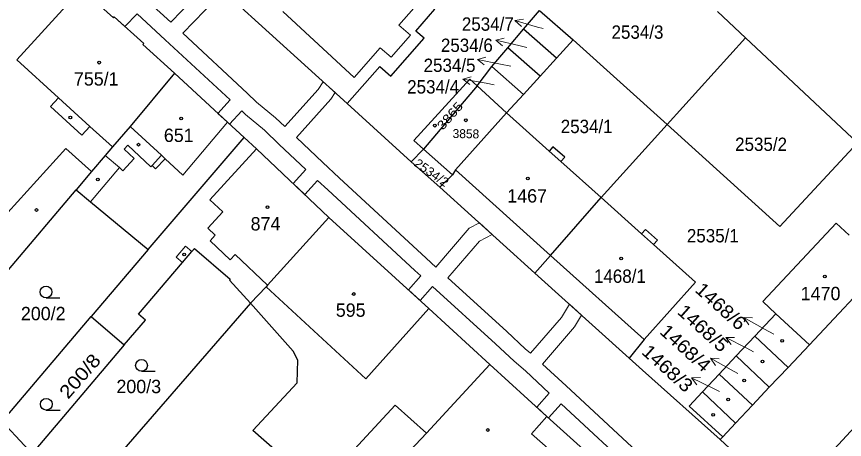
# Model space of a CAD drawing. Extents: x -679733 to -673243, y -1075091 to -1066557.
# Drawn here: x -676350.9 to -676245.5, y -1071162.3 to -1071108.5 of the extents above; entities that cross this region are included whole.
import ezdxf
from ezdxf.enums import TextEntityAlignment as Align

# ---------------------------------------------------------------- set-up
doc = ezdxf.new("R2010")
doc.units = 0
doc.header["$LTSCALE"] = 0.68
for name, color, linetype, lineweight in [('1', 7, 'Continuous', 25), ('13', 7, 'Continuous', 13), ('3', 7, 'Continuous', 25), ('4', 7, 'Continuous', 13), ('5', 7, 'Continuous', 25), ('7', 7, 'Continuous', 13)]:
    doc.layers.add(name, color=color, linetype=linetype, lineweight=lineweight)
doc.layers.add('2', color=7, linetype='Continuous')

msp = doc.modelspace()

# ---------------------------------------------------------------- linework, layer by layer
at = {"layer": '1'}
for p, q in [((-676323.75, -1071105.96), (-676308.77, -1071119.56)), ((-676286.33, -1071110.08), (-676284.31, -1071107.69)), ((-676284.31, -1071107.69), (-676280.02, -1071111.43)), ((-676282.12, -1071113.76), (-676286.33, -1071110.08)), ((-676268.05, -1071122.23), (-676258.07, -1071111.18)), ((-676284.22, -1071116.07), (-676288.34, -1071112.45)), ((-676286.33, -1071118.4), (-676290.36, -1071114.84)), ((-676292.22, -1071117.29), (-676299.05, -1071125.35)), ((-676292.22, -1071117.29), (-676288.48, -1071120.73)), ((-676308.77, -1071119.56), (-676300.62, -1071126.96)), ((-676295.38, -1071128.61), (-676299.05, -1071125.35)), ((-676295.38, -1071128.61), (-676296.99, -1071130.21)), ((-676352.68, -1071160), (-676341.37, -1071146.67)), ((-676249.94, -1071150.27), (-676254.22, -1071146.3)), ((-676252.66, -1071153.13), (-676256.88, -1071149.16)), ((-676337.15, -1071150.27), (-676348.88, -1071164.08)), ((-676255.04, -1071155.66), (-676259.26, -1071151.68)), ((-676257.2, -1071157.96), (-676261.43, -1071153.98)), ((-676260.97, -1071161.98), (-676261.28, -1071162.3))]:
    msp.add_line(p, q, dxfattribs=at)
for points in [[(-676352.93, -1071095.49), (-676342.59, -1071104.93), (-676338.52, -1071108.62), (-676338.42, -1071108.51), (-676334.67, -1071111.91), (-676334.77, -1071112.02), (-676330.76, -1071115.67)], [(-676308.77, -1071119.56), (-676304.62, -1071114.85), (-676303.22, -1071116.08), (-676298.98, -1071111.24), (-676300.04, -1071110.32), (-676297.6, -1071107.53), (-676298.57, -1071106.68), (-676296.84, -1071104.7), (-676301.82, -1071100.3), (-676301.85, -1071099.66), (-676302.05, -1071098.98), (-676302.33, -1071098.37), (-676302.65, -1071097.93), (-676303, -1071097.59), (-676303.32, -1071097.34)], [(-676261.62, -1071107.83), (-676258.07, -1071111.18), (-676243.8, -1071124.53), (-676238.45, -1071129.5), (-676236.29, -1071127.21), (-676234.12, -1071124.91), (-676233.88, -1071124.66), (-676231.56, -1071122.19), (-676229.54, -1071120.04)], [(-676290.36, -1071114.84), (-676288.34, -1071112.45), (-676286.33, -1071110.08)], [(-676268.05, -1071122.23), (-676280.02, -1071111.43), (-676282.12, -1071113.76), (-676284.22, -1071116.07)], [(-676293.17, -1071116.43), (-676292.22, -1071117.29), (-676290.36, -1071114.84)], [(-676330.76, -1071115.67), (-676336.39, -1071122.45), (-676338.67, -1071125.07), (-676339.6, -1071126.16), (-676341.33, -1071128.21), (-676343.28, -1071130.53)], [(-676330.76, -1071115.67), (-676324.03, -1071121.93), (-676321.9, -1071123.86)], [(-676300.62, -1071126.96), (-676299.05, -1071125.35), (-676300.28, -1071124.26), (-676293.17, -1071116.43)], [(-676284.22, -1071116.07), (-676286.33, -1071118.4), (-676288.48, -1071120.73)], [(-676288.48, -1071120.73), (-676294.99, -1071127.98), (-676295.38, -1071128.61)], [(-676276.45, -1071131.52), (-676281.57, -1071126.93), (-676281.09, -1071126.39), (-676282.58, -1071125.06), (-676283.06, -1071125.59), (-676288.48, -1071120.73)], [(-676243.8, -1071124.53), (-676253.69, -1071135.2), (-676268.05, -1071122.23), (-676276.45, -1071131.52)], [(-676343.28, -1071130.53), (-676341.44, -1071132.06), (-676334.13, -1071138.13), (-676321.9, -1071123.86)], [(-676321.9, -1071123.86), (-676320.3, -1071125.31), (-676311.12, -1071134.06)], [(-676296.99, -1071130.21), (-676298.47, -1071128.87), (-676300.62, -1071126.96)], [(-676261.28, -1071162.3), (-676271.19, -1071153.48), (-676272.88, -1071151.94), (-676284.89, -1071141.12), (-676296.99, -1071130.21)], [(-676360.58, -1071151.05), (-676352.91, -1071141.95), (-676351.88, -1071140.73), (-676343.28, -1071130.53)], [(-676284.89, -1071141.12), (-676282.91, -1071138.87), (-676276.45, -1071131.52)], [(-676276.45, -1071131.52), (-676271.31, -1071136.13), (-676270.81, -1071135.57), (-676269.28, -1071136.94), (-676269.78, -1071137.5), (-676264.42, -1071142.3), (-676270.96, -1071149.6), (-676272.88, -1071151.94)], [(-676311.12, -1071134.06), (-676318.9, -1071142.67), (-676319.1, -1071142.89), (-676321.1, -1071144.95)], [(-676311.12, -1071134.06), (-676298.38, -1071145.63), (-676290.61, -1071152.76)], [(-676204.87, -1071134.4), (-676225.85, -1071157.13), (-676233.8, -1071149.8), (-676237.15, -1071146.9), (-676235.55, -1071144.96), (-676240.55, -1071140.25), (-676249.94, -1071150.27), (-676252.66, -1071153.13), (-676255.04, -1071155.66), (-676257.2, -1071157.96)], [(-676254.22, -1071146.3), (-676255.85, -1071144.76), (-676246.53, -1071134.79), (-676244.88, -1071136.32)], [(-676334.13, -1071138.13), (-676341.37, -1071146.67), (-676337.15, -1071150.27)], [(-676337.15, -1071150.27), (-676334.47, -1071147.13), (-676335.36, -1071146.37), (-676329.74, -1071139.77), (-676328.57, -1071138.4), (-676328.23, -1071138.01), (-676323.67, -1071141.9), (-676323.77, -1071142.01), (-676321.1, -1071144.95)], [(-676321.1, -1071144.95), (-676343.05, -1071170.28), (-676338.56, -1071174.86)], [(-676308.33, -1071171.79), (-676309.88, -1071170.43), (-676312.17, -1071168.21), (-676312.43, -1071168.49), (-676320.8, -1071161.16), (-676315.15, -1071155.09), (-676315.05, -1071152.2), (-676315.65, -1071151.06), (-676321.1, -1071144.95)], [(-676261.43, -1071153.98), (-676259.26, -1071151.68), (-676256.88, -1071149.16), (-676254.22, -1071146.3)], [(-676302.23, -1071165.27), (-676298.66, -1071161.49), (-676290.61, -1071152.76)], [(-676290.61, -1071152.76), (-676283.35, -1071159.37), (-676279.12, -1071163.2), (-676277.21, -1071164.93), (-676274.24, -1071167.63)], [(-676260.97, -1071161.98), (-676265.26, -1071158.08), (-676263.54, -1071156.24), (-676261.43, -1071153.98)], [(-676257.2, -1071157.96), (-676259.34, -1071160.23), (-676260.97, -1071161.98)], [(-676348.88, -1071164.08), (-676349.85, -1071163.07), (-676352.68, -1071160)], [(-676261.28, -1071162.3), (-676252.88, -1071170.12), (-676253.02, -1071170.27), (-676249.35, -1071173.7), (-676249.45, -1071173.81), (-676249.16, -1071174.08), (-676249.26, -1071174.19), (-676246.82, -1071176.47), (-676246.72, -1071176.36), (-676238.5, -1071184.04), (-676238.61, -1071184.15), (-676238.42, -1071184.46), (-676236.41, -1071186.34), (-676236.16, -1071186.44), (-676236.06, -1071186.33), (-676235.7, -1071186.67), (-676235.59, -1071186.56), (-676231.81, -1071190.09), (-676230.87, -1071190.84), (-676229.69, -1071191.27), (-676228.42, -1071191.44), (-676227.02, -1071191.16), (-676225.61, -1071190.31)]]:
    msp.add_lwpolyline(points, dxfattribs=at)
at = {"layer": '13'}
for points in [[(-676327.02, -1071104.83), (-676331.24, -1071109.2), (-676334.83, -1071105.88)], [(-676270.15, -1071165.43), (-676280.89, -1071155.49), (-676283.93, -1071152.7), (-676279.83, -1071147.98), (-676278.93, -1071146.49), (-676280.49, -1071145.08), (-676281.51, -1071146.76), (-676285.46, -1071151.33), (-676286.11, -1071150.76), (-676288.45, -1071148.58), (-676295.96, -1071141.75), (-676291.95, -1071137.07), (-676290.32, -1071136.23), (-676291.95, -1071134.75), (-676293.25, -1071135.43), (-676297.49, -1071140.36), (-676298.72, -1071139.24), (-676309.78, -1071128.99), (-676311.89, -1071127.07), (-676315.24, -1071123.88), (-676310.84, -1071118.98), (-676310.31, -1071118.16), (-676311.84, -1071116.77), (-676312.46, -1071117.74), (-676316.72, -1071122.48), (-676317.91, -1071121.37), (-676320.3, -1071119.37), (-676321.5, -1071118.23), (-676329.71, -1071110.61), (-676325.48, -1071106.23)], [(-676338.7, -1071108.46), (-676338.52, -1071108.62), (-676338.42, -1071108.51), (-676337.08, -1071109.73), (-676335.52, -1071108.13), (-676331.93, -1071111.45), (-676323.69, -1071119.09), (-676325.25, -1071120.8), (-676324.03, -1071121.93), (-676323.75, -1071122.18), (-676322.2, -1071120.49), (-676321.72, -1071120.95), (-676319.31, -1071122.95), (-676317.42, -1071124.74), (-676314.06, -1071127.94), (-676315.66, -1071129.73), (-676314.18, -1071131.14), (-676312.56, -1071129.33), (-676311.22, -1071130.55), (-676300.16, -1071140.8), (-676299.41, -1071141.48), (-676300.99, -1071143.26), (-676299.48, -1071144.63), (-676297.9, -1071142.85), (-676289.89, -1071150.14), (-676287.53, -1071152.34), (-676286.08, -1071153.58), (-676283.08, -1071156.42), (-676284.64, -1071158.2), (-676283.35, -1071159.37), (-676283.13, -1071159.57), (-676281.55, -1071157.77), (-676271.55, -1071167.01)]]:
    msp.add_lwpolyline(points, dxfattribs=at)
at = {"layer": '3'}
for p, q in [((-676347.113, -1071144.28), (-676345.363, -1071144.28)), ((-676334.953, -1071153.63), (-676333.203, -1071153.63)), ((-676347.083, -1071158.57), (-676345.333, -1071158.57))]:
    msp.add_line(p, q, dxfattribs=at)
for centre in [(-676347.1129, -1071143.5298), (-676334.9529, -1071152.8798), (-676347.0829, -1071157.8198)]:
    msp.add_circle(centre, 0.75, dxfattribs=at)
at = {"layer": '4'}
for p, q in [((-676350.84, -1071114), (-676342.59, -1071104.93)), ((-676299.64, -1071106.67), (-676302.18, -1071109.57)), ((-676307.88, -1071116.22), (-676316.96, -1071107.84)), ((-676302.18, -1071109.57), (-676300.71, -1071110.86)), ((-676300.71, -1071110.86), (-676303.17, -1071113.66)), ((-676304.56, -1071112.44), (-676307.88, -1071116.22)), ((-676303.17, -1071113.66), (-676304.56, -1071112.44)), ((-676345.53, -1071118.82), (-676350.84, -1071114)), ((-676346.54, -1071119.93), (-676345.53, -1071118.82)), ((-676341.53, -1071122.47), (-676345.53, -1071118.82)), ((-676342.54, -1071123.57), (-676346.54, -1071119.93)), ((-676341.53, -1071122.47), (-676342.54, -1071123.57)), ((-676338.67, -1071125.07), (-676341.53, -1071122.47)), ((-676336.39, -1071122.45), (-676332.43, -1071126.13)), ((-676329.68, -1071128.68), (-676324.03, -1071121.93)), ((-676336.72, -1071124.86), (-676337.18, -1071125.35)), ((-676333.78, -1071127.61), (-676336.72, -1071124.86)), ((-676355.59, -1071137.36), (-676344.6, -1071125.25)), ((-676344.6, -1071125.25), (-676341.33, -1071128.21)), ((-676337.18, -1071125.35), (-676335.88, -1071126.56)), ((-676320.3, -1071125.31), (-676326.26, -1071131.79)), ((-676283.06, -1071125.59), (-676281.57, -1071126.93)), ((-676339.6, -1071126.16), (-676337.74, -1071127.7)), ((-676335.88, -1071126.56), (-676337.32, -1071128.1)), ((-676332.43, -1071126.13), (-676333.62, -1071127.43)), ((-676331.95, -1071126.57), (-676333.16, -1071127.86)), ((-676332.43, -1071126.13), (-676331.95, -1071126.57)), ((-676331.95, -1071126.57), (-676329.68, -1071128.68)), ((-676337.74, -1071127.7), (-676341.44, -1071132.06)), ((-676337.32, -1071128.1), (-676337.74, -1071127.7)), ((-676333.62, -1071127.43), (-676333.78, -1071127.61)), ((-676333.16, -1071127.86), (-676333.62, -1071127.43)), ((-676294.99, -1071127.98), (-676282.91, -1071138.87)), ((-676326.26, -1071131.79), (-676324.6, -1071133.34)), ((-676324.6, -1071133.34), (-676326.52, -1071135.41)), ((-676326.52, -1071135.41), (-676325.57, -1071136.31)), ((-676325.57, -1071136.31), (-676326.23, -1071137.01)), ((-676271.31, -1071136.13), (-676269.78, -1071137.5)), ((-676326.23, -1071137.01), (-676323.67, -1071139.44)), ((-676330.54, -1071139.09), (-676329.37, -1071137.72)), ((-676329.37, -1071137.72), (-676328.57, -1071138.4)), ((-676329.74, -1071139.77), (-676330.54, -1071139.09)), ((-676323.67, -1071139.44), (-676323.02, -1071138.75)), ((-676323.02, -1071138.75), (-676318.9, -1071142.67)), ((-676282.91, -1071138.87), (-676270.96, -1071149.6)), ((-676306.41, -1071154.58), (-676319.1, -1071142.89)), ((-676298.38, -1071145.63), (-676306.41, -1071154.58)), ((-676259.34, -1071160.23), (-676263.54, -1071156.24)), ((-676310.85, -1071166.78), (-676302.68, -1071157.92)), ((-676302.68, -1071157.92), (-676298.66, -1071161.49)), ((-676252.88, -1071170.12), (-676241.58, -1071157.91)), ((-676285.3, -1071161.58), (-676283.35, -1071159.37)), ((-676281.01, -1071165.37), (-676285.3, -1071161.58))]:
    msp.add_line(p, q, dxfattribs=at)
at = {"layer": '5'}
for centre in [(-676340.3468, -1071114.3392), (-676344.0168, -1071121.3292), (-676329.9068, -1071121.4592), (-676293.6768, -1071121.6792), (-676297.6068, -1071122.3592), (-676335.3368, -1071124.7792), (-676340.5268, -1071129.1992), (-676285.7768, -1071129.0892), (-676348.3168, -1071133.0992), (-676318.9068, -1071132.7292), (-676329.5368, -1071138.7592), (-676273.9068, -1071139.2592), (-676247.9568, -1071141.5492), (-676307.9468, -1071143.7892), (-676253.3868, -1071149.7492), (-676255.9168, -1071152.3892), (-676258.2368, -1071154.8092), (-676260.2868, -1071157.2292), (-676262.1768, -1071159.1592), (-676290.8768, -1071161.0992)]:
    msp.add_circle(centre, 0.175, dxfattribs=at)
at = {"layer": '7'}
for p, q in [((-676287.415, -1071108.993), (-676286.59, -1071109.75)), ((-676289.864, -1071111.495), (-676289.001, -1071112.208)), ((-676292.206, -1071113.947), (-676291.318, -1071114.63)), ((-676294.055, -1071116.449), (-676293.156, -1071117.116)), ((-676258.295, -1071146.795), (-676257.662, -1071147.719)), ((-676260.574, -1071149.328), (-676259.909, -1071150.228)), ((-676262.535, -1071151.975), (-676261.902, -1071152.899)), ((-676264.937, -1071154.444), (-676264.257, -1071155.334))]:
    msp.add_line(p, q, dxfattribs=at)
for points in [[(-676283.84, -1071110.01), (-676284.53, -1071109.82), (-676287.415, -1071108.993), (-676286.314, -1071108.788)], [(-676285.89, -1071112.42), (-676286.94, -1071112.17), (-676289.864, -1071111.495), (-676288.776, -1071111.232)], [(-676287.95, -1071114.77), (-676289.26, -1071114.52), (-676292.206, -1071113.947), (-676291.127, -1071113.647)], [(-676290.06, -1071117.15), (-676291.1, -1071116.97), (-676294.055, -1071116.449), (-676292.982, -1071116.13)], [(-676254.45, -1071148.92), (-676255.67, -1071148.25), (-676258.295, -1071146.795), (-676257.176, -1071146.843)], [(-676257.04, -1071151.13), (-676257.9, -1071150.69), (-676260.574, -1071149.328), (-676259.454, -1071149.336)], [(-676259.03, -1071153.92), (-676259.91, -1071153.43), (-676262.535, -1071151.975), (-676261.416, -1071152.023)], [(-676261.38, -1071156.18), (-676262.24, -1071155.76), (-676264.937, -1071154.444), (-676263.818, -1071154.433)]]:
    msp.add_lwpolyline(points, dxfattribs=at)

# ---------------------------------------------------------------- texts
at = {"layer": '2', "width": 0.95}
for s, p in [('2534/7', (-676287.57, -1071110.279)), ('2534/6', (-676290.24, -1071112.979)), ('2534/5', (-676292.44, -1071115.529)), ('2534/4', (-676294.53, -1071118.269))]:
    msp.add_text(s, height=1.7, dxfattribs=at).set_placement(p, align=Align.RIGHT)
for s, p in [('2534/3', (-676271.819, -1071111.3)), ('2534/1', (-676278.289, -1071123.31)), ('2535/2', (-676256.089, -1071125.58)), ('2535/1', (-676262.229, -1071137.22)), ('1468/1', (-676274.059, -1071142.37))]:
    msp.add_text(s, height=1.7, dxfattribs=at).set_placement(p, align=Align.CENTER)
at = {"layer": '2'}
for s, p in [('755/1', (-676340.72, -1071117.259)), ('651', (-676330.219, -1071124.44)), ('1467', (-676285.87, -1071132.15)), ('874', (-676319.169, -1071135.7)), ('1470', (-676248.51, -1071144.58)), ('595', (-676308.329, -1071146.69)), ('200/2', (-676347.47, -1071147.13)), ('200/3', (-676335.31, -1071156.41))]:
    msp.add_text(s, height=1.7, dxfattribs=at).set_placement(p, align=Align.CENTER)
for s, height, rotation, width, p in [('3865', 1.139, 49, 1.2, (-676295.2634, -1071121.4741)), ('2534/2', 1.139, 325, 1.05, (-676298.3482, -1071128.8087)), ('200/8', 1.7, 49, 1.15, (-676342.1543, -1071154.7951))]:
    msp.add_text(s, height=height, rotation=rotation, dxfattribs=dict(at, width=width)).set_placement(p, align=Align.CENTER)
msp.add_text('3858', height=1.139, rotation=359, dxfattribs=at).set_placement((-676293.6724, -1071123.9594), align=Align.CENTER)
at = {"layer": '2', "width": 1.1}
for s, p in [('1468/6', (-676258.9305, -1071148.5336)), ('1468/5', (-676261.1905, -1071151.3236)), ('1468/4', (-676263.4305, -1071153.8536)), ('1468/3', (-676265.7205, -1071156.4336))]:
    msp.add_text(s, height=1.7, rotation=318, dxfattribs=at).set_placement(p, align=Align.RIGHT)

doc.saveas('drawing.dxf')
